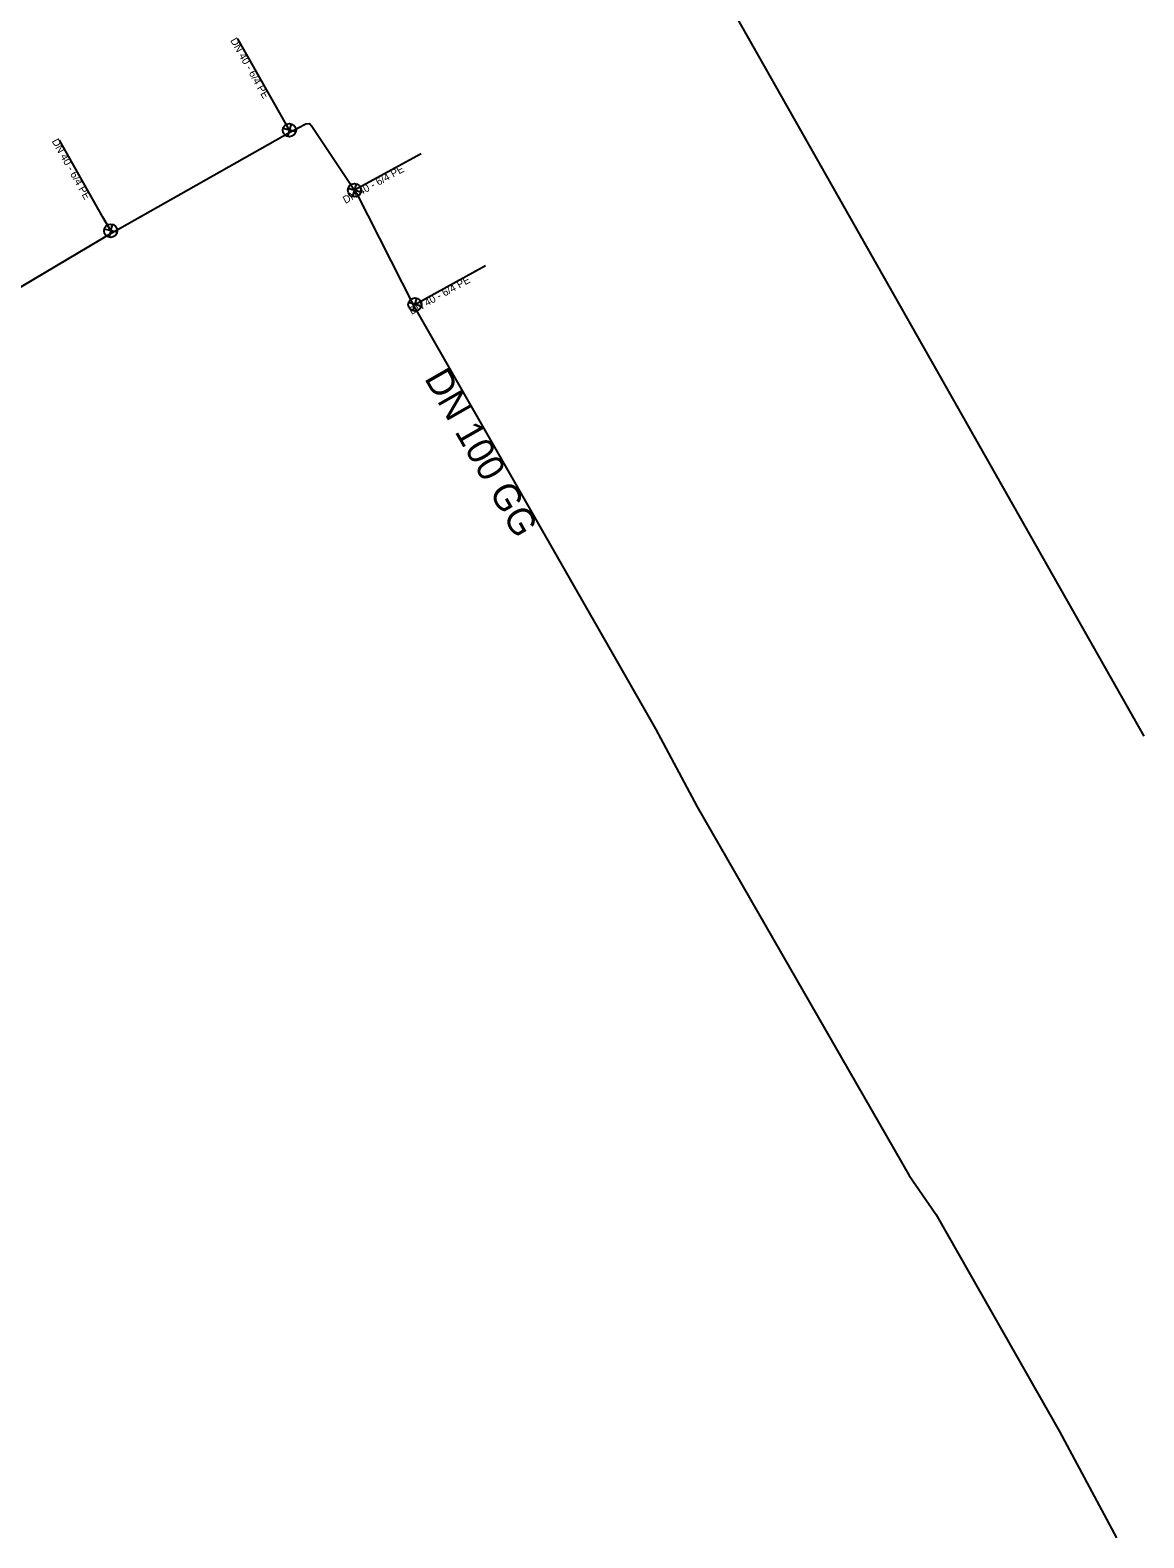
# Model space of a CAD drawing. Extents: x -443562 to -443270, y -1122830 to -1122511.
# Drawn here: x -443336.9 to -443269.8, y -1122829.6 to -1122738.8 of the extents above; entities that cross this region are included whole.
import ezdxf

# ---------------------------------------------------------------- set-up
doc = ezdxf.new("R2010")
doc.units = 0
for name, color, linetype in [('_pripojka_priblizne_', 7, 'Continuous'), ('_voda_smvak_prevzato_z_dokumentace_', 7, 'Continuous'), ('Default', 7, 'Continuous'), ('MoLevel 32', 7, 'Continuous'), ('MoLevel 46', 7, 'Continuous'), ('MoLevel 53', 7, 'Continuous')]:
    doc.layers.add(name, color=color, linetype=linetype)

# ---------------------------------------------------------------- blocks, each defined once
blk = doc.blocks.new('_uzaver_pripojka_')
at = {"layer": 'Default'}
for p, q in [((-0.000035, -0.000035), (0.000035, 0.000035)), ((0.000035, -0.000035), (-0.000035, 0.000035))]:
    blk.add_line(p, q, dxfattribs=at)
for radius in [0.00005, 0.0000025]:
    blk.add_circle((0, 0), radius, dxfattribs=at)

msp = doc.modelspace()

# ---------------------------------------------------------------- linework, layer by layer
at = {"layer": '_pripojka_priblizne_'}
msp.add_line((-443313.34, -1122746.25), (-443317.348, -1122748.453), dxfattribs=at)
for points in [[(-443321.2, -1122744.93), (-443321.27, -1122744.83), (-443324.374, -1122739.33)], [(-443331.96, -1122751.02), (-443332.03, -1122750.89), (-443332.5, -1122750.08), (-443335.106, -1122745.432)], [(-443313.793, -1122755.399), (-443313.71, -1122755.33), (-443309.459, -1122752.977)]]:
    msp.add_lwpolyline(points, dxfattribs=at)
at = {"layer": '_voda_smvak_prevzato_z_dokumentace_'}
msp.add_line((-443310.987, -1122708.637), (-443269.826, -1122781.333), dxfattribs=at)
msp.add_lwpolyline([(-443367.56, -1122742.07), (-443355.37, -1122764.139), (-443355.102, -1122764.316), (-443354.703, -1122764.296), (-443347.45, -1122760.22), (-443331.96, -1122751.02), (-443321.2, -1122744.93), (-443320.285, -1122744.451), (-443320.06, -1122744.427), (-443319.914, -1122744.58), (-443317.228, -1122748.634), (-443313.793, -1122755.399), (-443299.23, -1122780.89), (-443296.72, -1122785.58), (-443283.95, -1122807.8), (-443282.35, -1122810.12), (-443274.899, -1122823.22), (-443271.477, -1122829.619)], dxfattribs=at)

# ---------------------------------------------------------------- block references
at = {"layer": 'MoLevel 53'}
for p, xscale, yscale, rotation in [((-443321.27, -1122744.83), 7999.999999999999, 7999.999999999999, 119.43767474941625), ((-443317.348, -1122748.453), 8000, 8000, 28.78428755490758), ((-443332.03, -1122750.89), 7999.999999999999, 8000.000000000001, 121.2098415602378), ((-443313.71, -1122755.33), 7999.999999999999, 8000, 28.96474695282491)]:
    msp.add_blockref('_uzaver_pripojka_', p, dxfattribs=dict(at, xscale=xscale, yscale=yscale, rotation=rotation))

# ---------------------------------------------------------------- texts
at = {"layer": 'MoLevel 32'}
for rotation, p in [(299.43768, (-443324.845, -1122739.421)), (299.27412, (-443335.591, -1122745.496)), (28.79367, (-443317.898, -1122749.274)), (28.97408, (-443313.911, -1122755.962))]:
    msp.add_text('DN 40 - 6/4 PE', height=0.455, rotation=rotation, dxfattribs=at).set_placement(p)
at = {"layer": 'MoLevel 46'}
msp.add_text('DN 100 GG', height=1.6049, rotation=299.73977, dxfattribs=at).set_placement((-443313.175, -1122759.776))

doc.saveas('drawing.dxf')
